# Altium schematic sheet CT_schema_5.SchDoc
size 454 x 430 mm
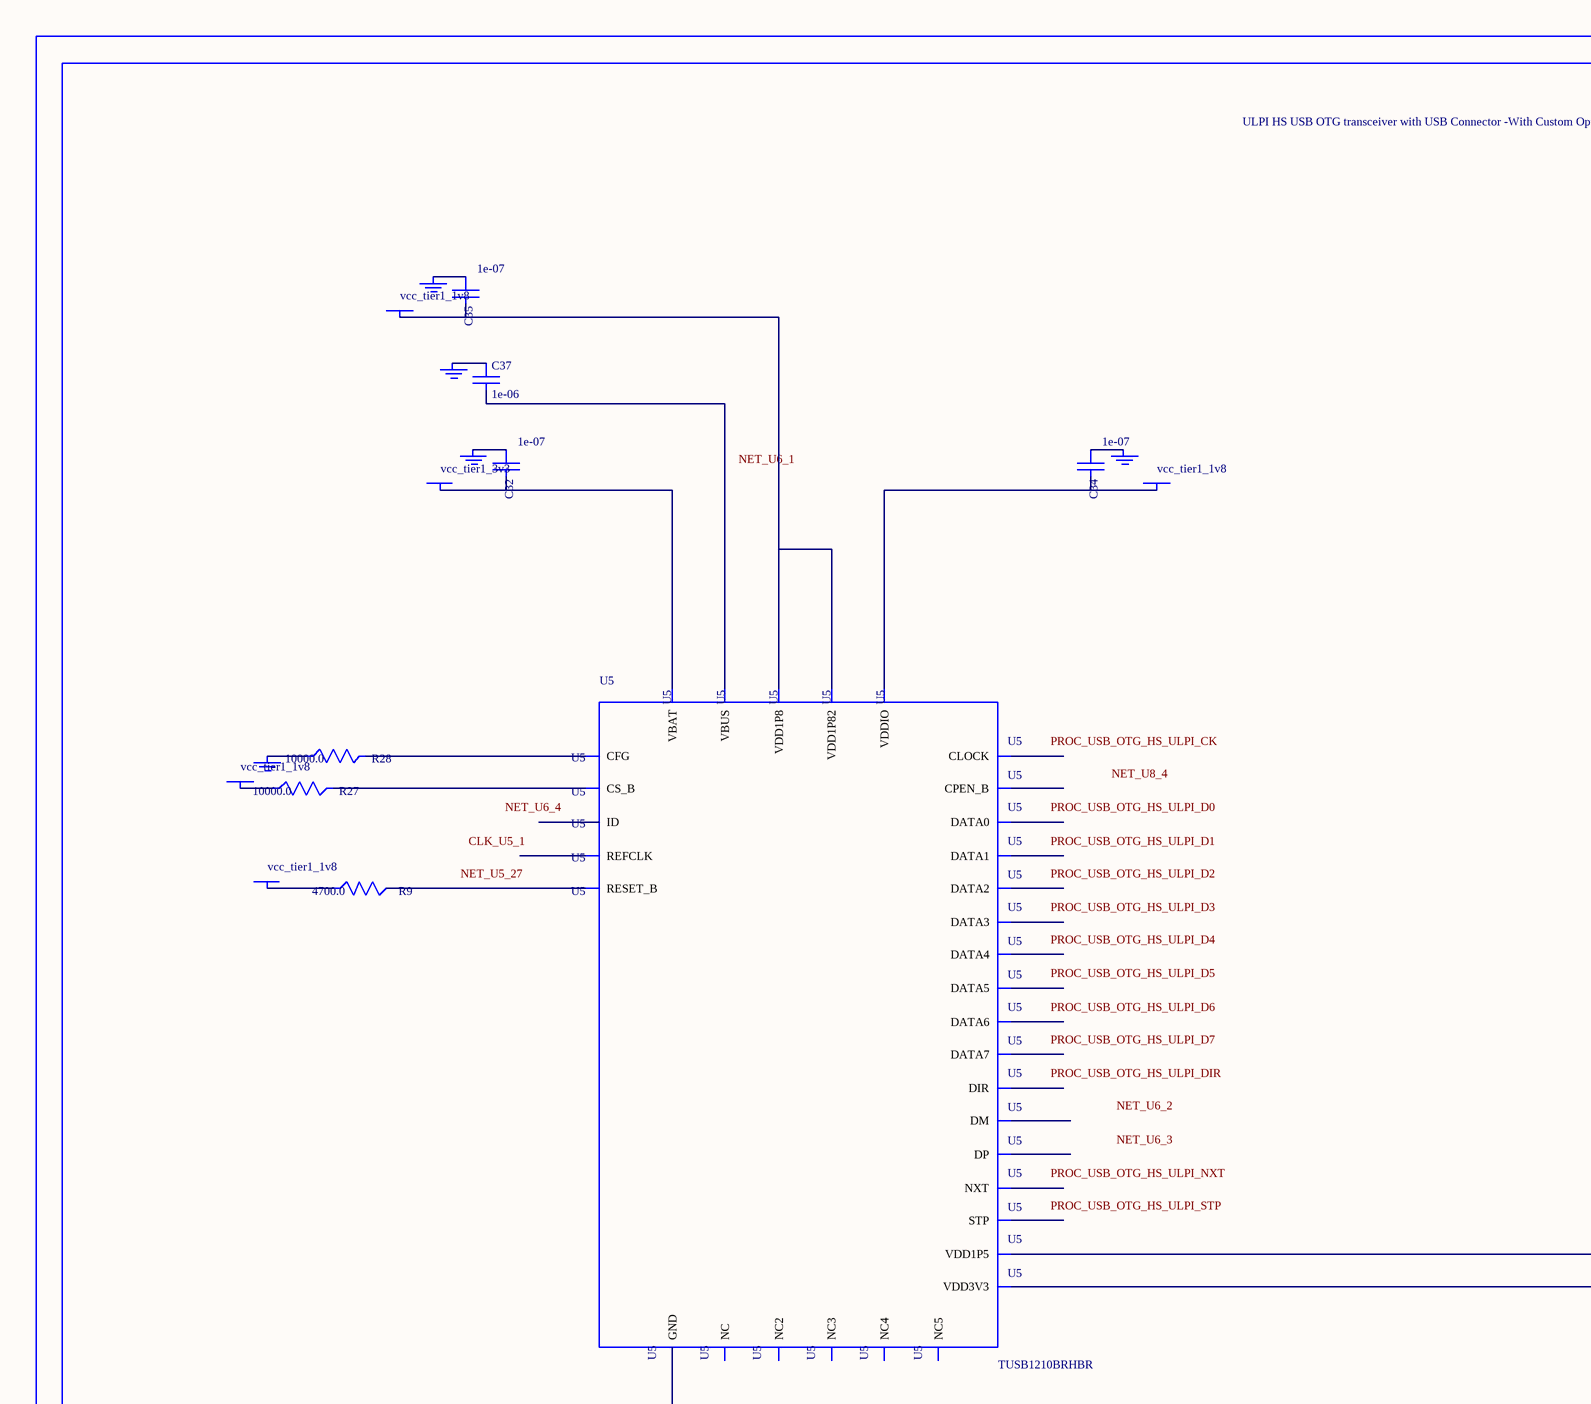
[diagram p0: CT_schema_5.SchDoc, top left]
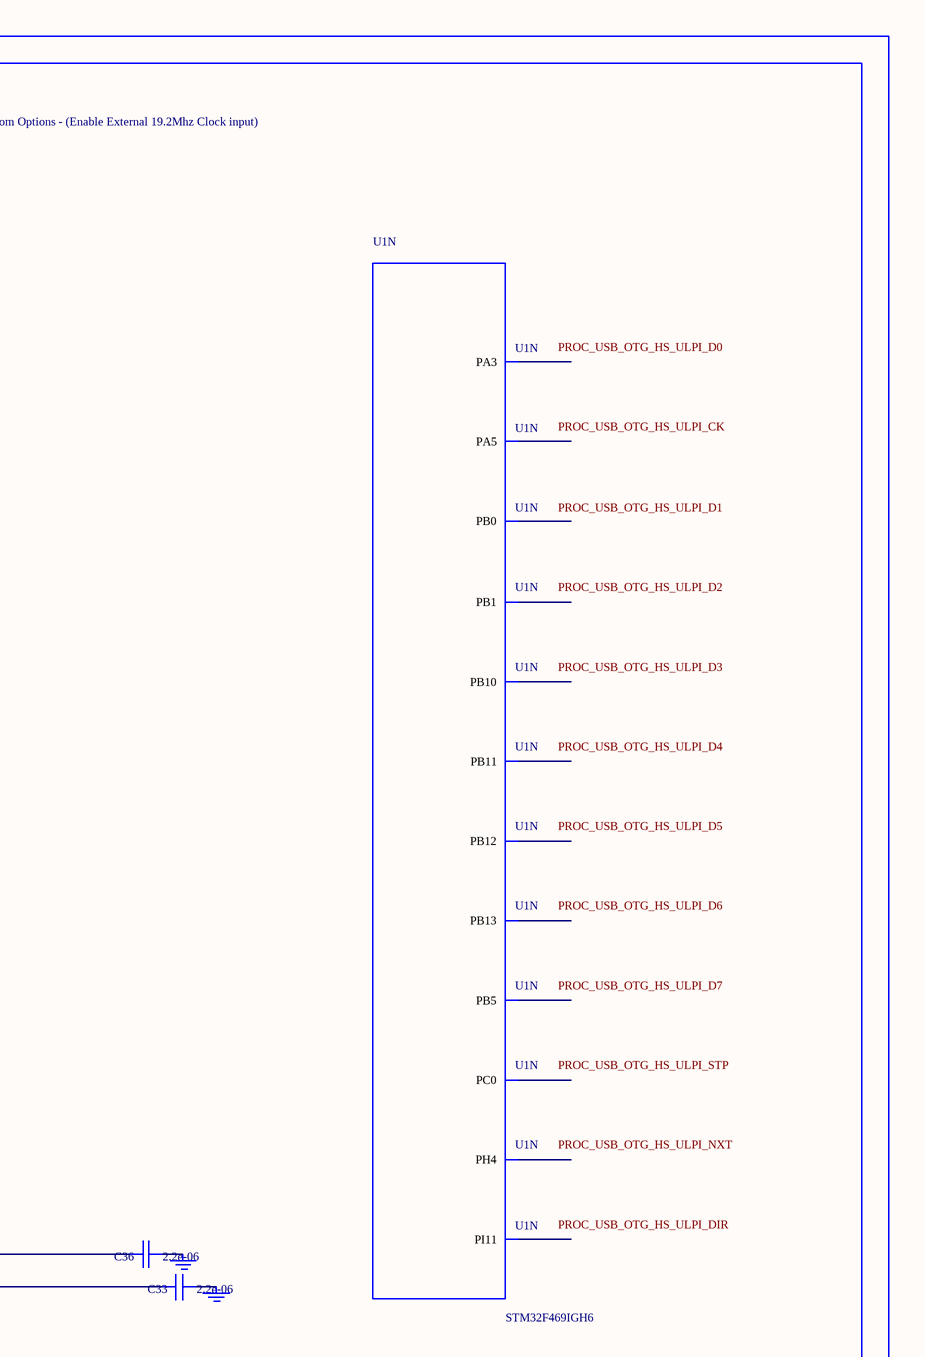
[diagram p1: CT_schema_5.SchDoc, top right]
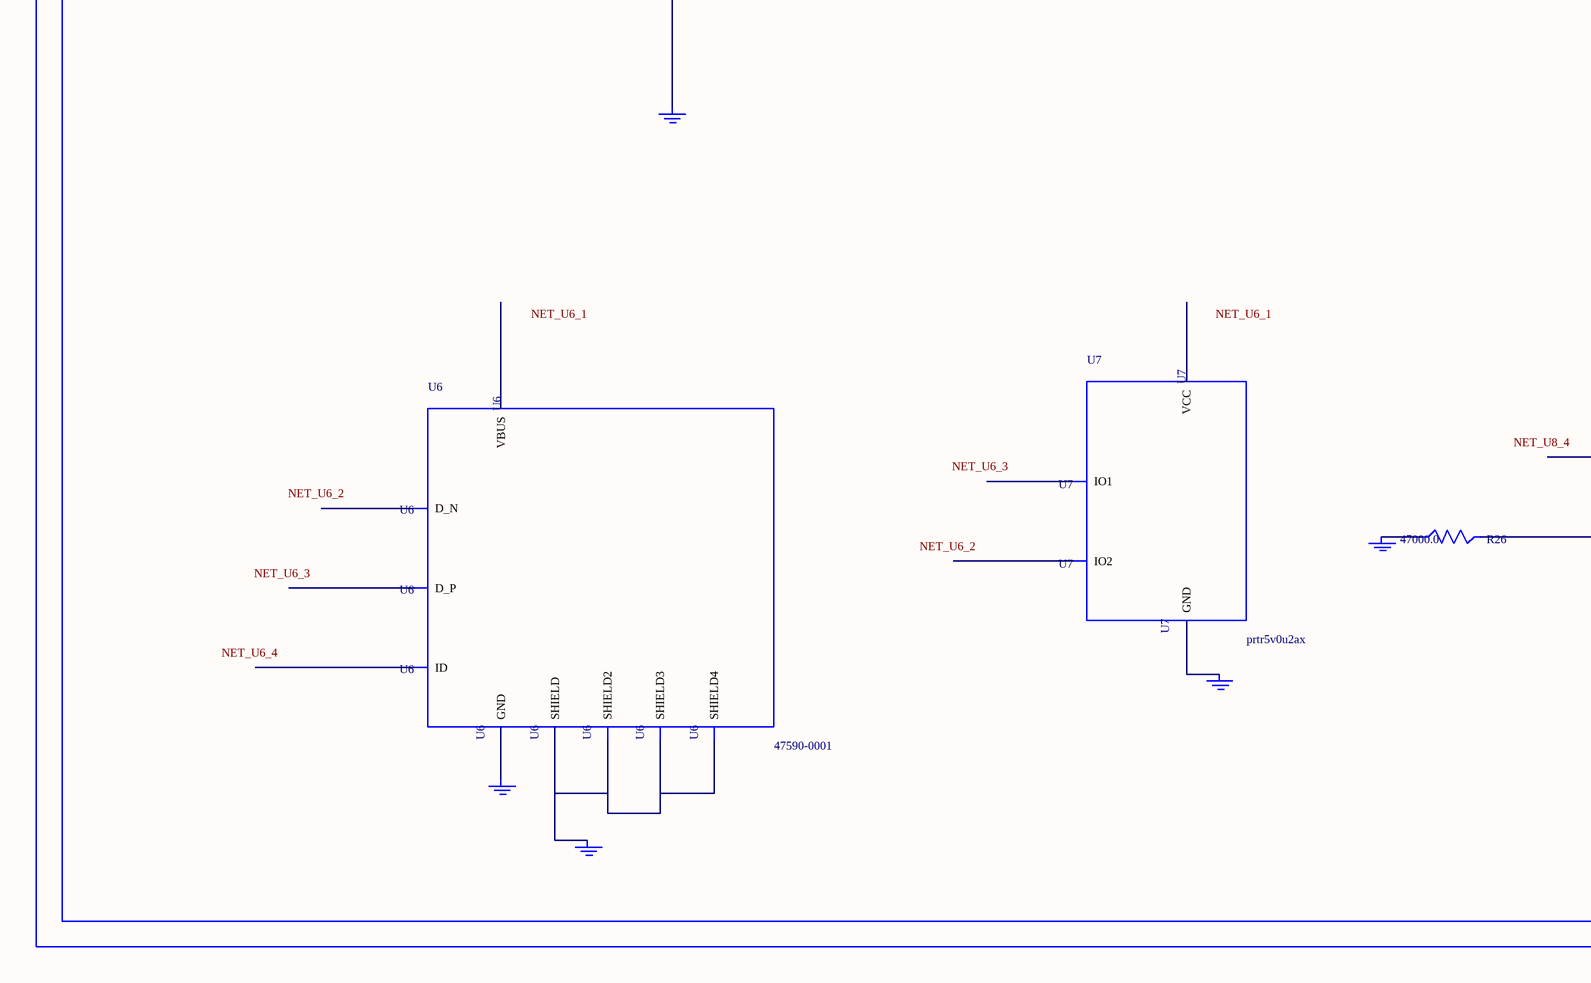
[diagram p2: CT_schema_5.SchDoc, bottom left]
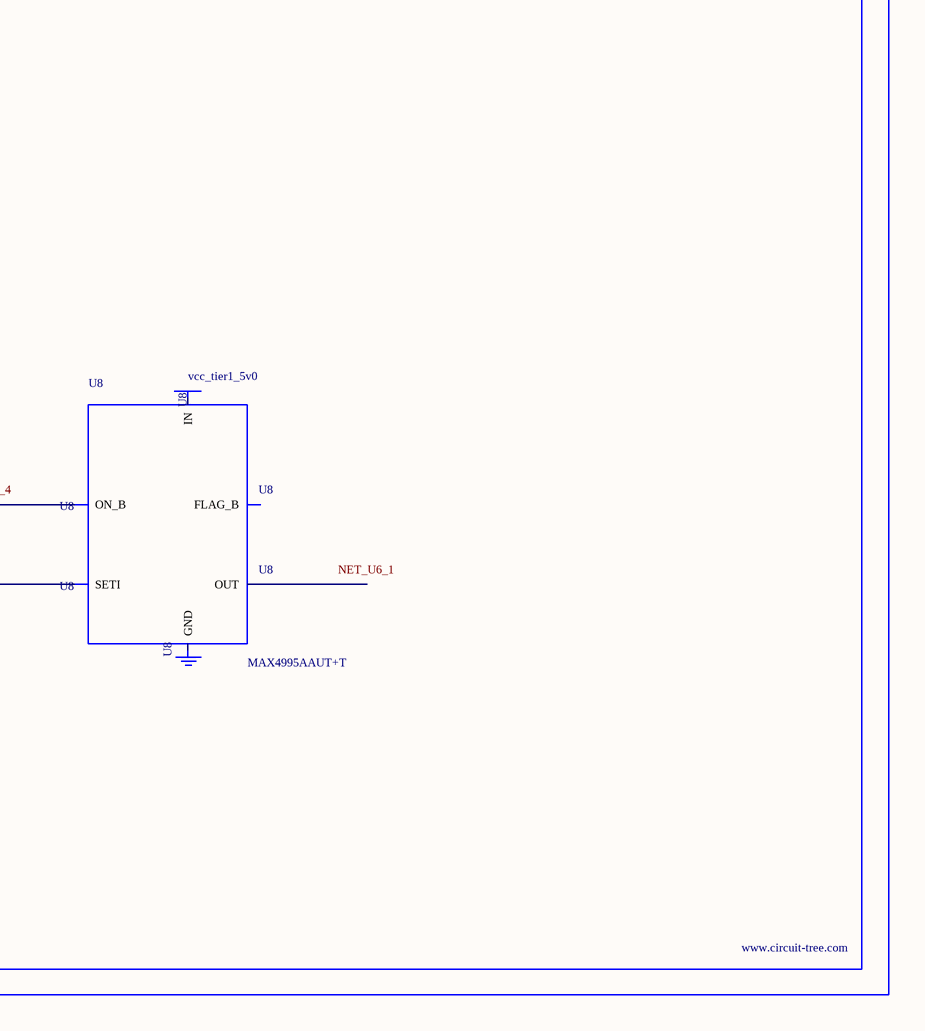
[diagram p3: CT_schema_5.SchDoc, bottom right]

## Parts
BORDER4  (no value)
C32  1e-07  [C0402]
C33  2.2e-06  [C0603]
C34  1e-07  [C0402]
C35  1e-07  [C0402]
C36  2.2e-06  [C0603]
C37  1e-06  [C0603]
GND_INSTANCE_4_0  (no value)
GND_INSTANCE_4_1  (no value)
GND_INSTANCE_4_2  (no value)
GND_INSTANCE_4_3  (no value)
GND_INSTANCE_4_4  (no value)
GND_INSTANCE_4_5  (no value)
GND_INSTANCE_4_6  (no value)
GND_INSTANCE_4_7  (no value)
GND_INSTANCE_4_8  (no value)
GND_INSTANCE_4_9  (no value)
GND_INSTANCE_4_10  (no value)
GND_INSTANCE_4_11  (no value)
GND_INSTANCE_4_12  (no value)
POWER_INSTANCE_4_0  vcc_tier1_1v8
POWER_INSTANCE_4_1  vcc_tier1_3v3
POWER_INSTANCE_4_2  vcc_tier1_1v8
POWER_INSTANCE_4_3  vcc_tier1_1v8
POWER_INSTANCE_4_4  vcc_tier1_1v8
POWER_INSTANCE_4_5  vcc_tier1_5v0
R9  4700.0  [R0603]
R26  47000.0  [R0603]
R27  10000.0  [R0603]
R28  10000.0  [R0603]
U1  STM32F469IGH6  [UFBGA176]  (part N of 16)
U5  TUSB1210BRHBR  [RHB32_3P45X3P45]
U6  47590-0001  [MICRO_USB_AB]
U7  prtr5v0u2ax  [SOT143B]
U8  MAX4995AAUT+T  [SOT-23-6]

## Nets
NetC32_1: C32.1 GND_INSTANCE_4_3.0(GND)
NetC32_2: C32.2 POWER_INSTANCE_4_1.0(PWR) U5.21(VBAT)
NetC33_1: C33.1 GND_INSTANCE_4_2.0(GND)
NetC33_2: C33.2 U5.20(VDD3V3)
NetC34_1: C34.1 GND_INSTANCE_4_6.0(GND)
NetC34_2: C34.2 POWER_INSTANCE_4_3.0(PWR) U5.32(VDDIO)
NetC35_1: C35.1 GND_INSTANCE_4_5.0(GND)
NetC35_2: C35.2 POWER_INSTANCE_4_2.0(PWR) U5.28(VDD1P8) U5.30(VDD1P82)
NetC36_1: C36.1 GND_INSTANCE_4_0.0(GND)
NetC36_2: C36.2 U5.12(VDD1P5)
NetC37_1: C37.1 GND_INSTANCE_4_4.0(GND)
NetC37_2: C37.2 U5.22(VBUS)
NetGND_INSTANCE_4_1_0: GND_INSTANCE_4_1.0(GND) R28.1
NetGND_INSTANCE_4_7_0: GND_INSTANCE_4_7.0(GND) U5.33(GND)
NetGND_INSTANCE_4_8_0: GND_INSTANCE_4_8.0(GND) U6.6(SHIELD) U6.7(SHIELD2) U6.8(SHIELD3) U6.9(SHIELD4)
NetGND_INSTANCE_4_9_0: GND_INSTANCE_4_9.0(GND) U6.5(GND)
NetGND_INSTANCE_4_10_0: GND_INSTANCE_4_10.0(GND) U7.1(GND)
NetGND_INSTANCE_4_11_0: GND_INSTANCE_4_11.0(GND) R26.1
NetPOWER_INSTANCE_4_0_0: POWER_INSTANCE_4_0.0(PWR) R27.1
NetPOWER_INSTANCE_4_4_0: POWER_INSTANCE_4_4.0(PWR) R9.1
NetR9_2: R9.2 U5.27(RESET_B)
NetR26_2: R26.2 U8.3(SETI)
NetR27_2: R27.2 U5.11(CS_B)
NetR28_2: R28.2 U5.14(CFG)

Not connected (* = marked no-connect by the designer): GND_INSTANCE_4_12 0(GND); POWER_INSTANCE_4_5 0(PWR); U1 A6(PB5) E4(PI11) H4(PH4) M2(PC0) P4(PA5) P12(PB12) P13(PB13) R2(PA3) R4(PB1) R5(PB0) R12(PB10) R13(PB11); U5 1(REFCLK) 2(NXT) 3(DATA0) 4(DATA1) 5(DATA2) 6(DATA3) 7(DATA4) 8(NC) 9(DATA5) 10(DATA6) 13(DATA7) 15(NC2) 16(NC3) 17(CPEN_B) 18(DP) 19(DM) 23(ID) 24(NC4) 25(NC5) 26(CLOCK) 29(STP) 31(DIR); U6 1(VBUS) 2(D_N) 3(D_P) 4(ID); U7 2(IO1) 3(IO2) 4(VCC); U8 1(OUT) 2(GND) 4(ON_B) 5(IN) 6(FLAG_B)

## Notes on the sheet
- Labels drawn without touching a wire or pin: CLK_U5_1, NET_U5_27, NET_U6_1, NET_U6_2, NET_U6_3, NET_U6_4, NET_U8_4, PROC_USB_OTG_HS_ULPI_CK, PROC_USB_OTG_HS_ULPI_D0, PROC_USB_OTG_HS_ULPI_D1, PROC_USB_OTG_HS_ULPI_D2, PROC_USB_OTG_HS_ULPI_D3, PROC_USB_OTG_HS_ULPI_D4, PROC_USB_OTG_HS_ULPI_D5, PROC_USB_OTG_HS_ULPI_D6, PROC_USB_OTG_HS_ULPI_D7, PROC_USB_OTG_HS_ULPI_DIR, PROC_USB_OTG_HS_ULPI_NXT, PROC_USB_OTG_HS_ULPI_STP

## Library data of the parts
BORDER4 = BORDER_PAGE4
C32 C34 C35 = C0402C104K3RACTU
C33 C36 = C0603C225K8RACTU
C37 = C0603C105K3RACTU
GND_INSTANCE_4_0-GND_INSTANCE_4_12 = GND
POWER_INSTANCE_4_0-POWER_INSTANCE_4_5 = PWR
R9 = RC0603JR-074K7L
R26 = RC0603JR-0747KL
R27 R28 = RC0603JR-0710KL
